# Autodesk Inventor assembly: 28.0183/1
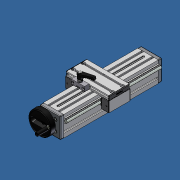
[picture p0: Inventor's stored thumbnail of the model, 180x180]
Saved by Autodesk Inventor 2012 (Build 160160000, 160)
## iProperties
Created: 2007-06
Part Number: 28.0183/1
Document SubType Name: Assembly
Designer: Andy Moles
Description: ADJUSTING UNIT VEW 90 WITH TOP LOCK
Author: Andy Moles
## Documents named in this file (20)
- C:\Andys Backup Data\ANDY'S INVENTOR\INVENTOR LIBRARIES\PARTS LIBRARY\READY FOR USE MODULES LG\28.0183_1 ADJUSTING UNIT VEW 90 WITH TOP LOCK.iam
- C:\Andys Backup Data\ANDY'S INVENTOR\INVENTOR LIBRARIES\PARTS LIBRARY\FASTENING ELEMENTS\NUTS\21.1351 M8 SQUARE NUT.ipt
- C:\Andys Backup Data\ANDY'S INVENTOR\INVENTOR LIBRARIES\PARTS LIBRARY\READY FOR USE MODULES LG\SUBCOMPONENTS\50.1264 BALL BEARING 10X30X9 6200 2RS DIN 625.ipt
- C:\Andys Backup Data\ANDY'S INVENTOR\INVENTOR LIBRARIES\PARTS LIBRARY\READY FOR USE MODULES LG\SUBCOMPONENTS\28.0204 HANDWHEEL 100mm.iam
- C:\Andys Backup Data\ANDY'S INVENTOR\INVENTOR LIBRARIES\PARTS LIBRARY\READY FOR USE MODULES LG\SUBCOMPONENTS\28.0205 BEARING PLATE 90X90 HANDWHEEL SIDE.ipt
- C:\Andys Backup Data\ANDY'S INVENTOR\INVENTOR LIBRARIES\PARTS LIBRARY\READY FOR USE MODULES LG\SUBCOMPONENTS\28.0206 BEARING PLATE 90X90 IDLER SIDE.ipt
- C:\Andys Backup Data\ANDY'S INVENTOR\INVENTOR LIBRARIES\PARTS LIBRARY\FASTENING ELEMENTS\SCREWS CAP\21.1204 M8X25.ipt
- C:\Andys Backup Data\ANDY'S INVENTOR\INVENTOR LIBRARIES\PARTS LIBRARY\READY FOR USE MODULES LG\SUBCOMPONENTS\28.0216_2 90x90 RAIL TOP LOCK.iam
- C:\Andys Backup Data\ANDY'S INVENTOR\INVENTOR LIBRARIES\PARTS LIBRARY\FASTENING ELEMENTS\WASHERS\21.1326 DISC SPRING 20.ipt
- C:\Andys Backup Data\ANDY'S INVENTOR\INVENTOR LIBRARIES\PARTS LIBRARY\READY FOR USE MODULES LG\SUBCOMPONENTS\28.0221_1 ACME SCREW 16X4 TOP LOCK.ipt
- C:\Andys Backup Data\ANDY'S INVENTOR\INVENTOR LIBRARIES\PARTS LIBRARY\READY FOR USE MODULES LG\SUBCOMPONENTS\28.0225_1 LWG 32X45-90 90X19-NSC.ipt
- C:\Andys Backup Data\ANDY'S INVENTOR\INVENTOR LIBRARIES\PARTS LIBRARY\READY FOR USE MODULES LG\SUBCOMPONENTS\28.0126 SLIDE 45X32.ipt
- C:\Andys Backup Data\ANDY'S INVENTOR\INVENTOR LIBRARIES\PARTS LIBRARY\FASTENING ELEMENTS\SCREWS CAP\21.1200 M8X16.ipt
- C:\Andys Backup Data\ANDY'S INVENTOR\INVENTOR LIBRARIES\PARTS LIBRARY\FASTENING ELEMENTS\SCREWS CAP\21.1235 M5X16.ipt
- C:\Andys Backup Data\ANDY'S INVENTOR\INVENTOR LIBRARIES\PARTS LIBRARY\COMPONENTS LG\22.1094 SLIDE RAIL LG.iam
- C:\Andys Backup Data\ANDY'S INVENTOR\INVENTOR LIBRARIES\PARTS LIBRARY\READY FOR USE MODULES LG\SUBCOMPONENTS\28.0255 Nut slide connector 20.ipt
- C:\Andys Backup Data\ANDY'S INVENTOR\INVENTOR LIBRARIES\PARTS LIBRARY\COMPONENTS LR\28.0270_9 SLIDE CLAMPING UNIT 2mm OFFSET..iam
- C:\Andys Backup Data\ANDY'S INVENTOR\INVENTOR LIBRARIES\PARTS LIBRARY\END CAPS\22.1003_1 END CAP 45x32 Z Gray.iam
- C:\Andys Backup Data\ANDY'S INVENTOR\INVENTOR LIBRARIES\PARTS LIBRARY\END CAPS\22.1014_1 END CAP 90X19 GRAY.ipt
- C:\Andys Backup Data\ANDY'S INVENTOR\INVENTOR LIBRARIES\PARTS LIBRARY\READY FOR USE MODULES LG\SUBCOMPONENTS\28.0257 BRONZE NUT 16X4 NOTCHED.ipt
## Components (41 placed, 19 different names)
1. 28.0216_2 90x90 RAIL TOP LOCK:1 [sub-assembly] — Mate:8, Flush:4, Mate:9, Flush:5, Flush:6, Flush:7, Mate:10, Mate:13, Flush:8, Flush:9, Angle:10, Mate:31
2. 50.1264 10X30X9 6200 2RS DIN 625 BALL BEARING:1 — Insert:15, Insert:18
3. 50.1264 10X30X9 6200 2RS DIN 625 BALL BEARING:2 — Insert:14
4. 28.0204 HANDWHEEL 100mm:1 [sub-assembly] — Insert:5, Angle:3, Angle:4
5. 28.0205 BEARING PLATE 90X90 HANDWHEEL SIDE:1 — Insert:5, Insert:6, Insert:7, Insert:8, Insert:9, Insert:15, Flush:5, Flush:7, Mate:10, Angle:4, Angle:11
6. 28.0206 BEARING PLATE 90X90 IDLER SIDE:1 — Insert:10, Insert:11, Insert:12, Insert:13, Insert:14, Flush:6, Mate:13, Flush:8, Flush:9
7. 21.1204  M8 x 25:1 — Insert:6
8. 21.1204  M8 x 25:2 — Insert:7
9. 21.1204  M8 x 25:3 — Insert:8
10. 21.1204  M8 x 25:4 — Insert:13
11. 21.1204  M8 x 25:5 — Insert:9
12. 21.1204  M8 x 25:6 — Insert:12
13. 21.1204  M8 x 25:7 — Insert:11
14. 21.1204  M8 x 25:8 — Insert:10
15. 21.1326 DISC SPRING 20:1 — Insert:17
16. 21.1326 DISC SPRING 20:2 — Insert:16, Insert:18
17. 28.0221_1 ACME SCREW 16X4 TOP LOCK:1 — Insert:16, Insert:17, Angle:3, Mate:33
18. 28.0225_1 LWG 32X45-90 90X19-NSC:1 — Insert:19, Insert:20, Insert:21, Insert:22, Insert:23, Insert:24, Insert:25, Insert:26, Angle:5, Angle:6, Angle:7, Angle:8, Mate:17, Flush:10, Mate:18, Flush:11, Flush:12, Flush:13, Insert:27, Insert:28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
19. 28.0126 SLIDE 45X32:1 — Mate:18, Flush:11, Flush:12, Mate:19, Flush:14, Mate:20, Mate:26, Flush:19, Flush:20, Mate:28, Flush:23, Flush:24
20. 28.0126 SLIDE 45X32:2 — Mate:17, Flush:10, Flush:13, Mate:21, Flush:15, Mate:22, Mate:25, Flush:17, Flush:18, Mate:27, Flush:21, Flush:22
21. 21.1200 M8 x 16:1 — Insert:20
22. 21.1200 M8 x 16:2 — Insert:19
23. 21.1200 M8 x 16:3 — Insert:21
24. 21.1200 M8 x 16:4 — Insert:22
25. 21.1351 M8 SQUARE NUT:2 — Insert:23, Angle:8
26. 21.1351 M8 SQUARE NUT:3 — Insert:24, Angle:7
27. 21.1351 M8 SQUARE NUT:4 — Insert:25, Angle:6
28. 21.1351 M8 SQUARE NUT:5 — Insert:26, Angle:5
29. 21.1235  M5 x 16:1 — Insert:28
30. 21.1235  M5 x 16:2 — Insert:27
31. 22.1094 SLIDE RAIL LG:1 [sub-assembly] — Mate:19, Flush:14, Mate:20
32. 22.1094 SLIDE RAIL LG:2 [sub-assembly] — Mate:21, Flush:15, Mate:22, Mate:31
33. 28.0255 Nut slide connector 20:1 — Insert:29, Angle:9, Mate:32, Angle:12
34. 28.0270_9 SLIDE CLAMPING UNIT 2mm OFFSET.:1 [sub-assembly] — Mate:23, Mate:24, Flush:16
35. 22.1003\1 END CAP 45x32 Z Gray:1 [sub-assembly] — Mate:26, Flush:19, Flush:20
36. 22.1003\1 END CAP 45x32 Z Gray:2 [sub-assembly] — Mate:25, Flush:17, Flush:18
37. 22.1003\1 END CAP 45x32 Z Gray:3 [sub-assembly] — Mate:28, Flush:23, Flush:24
38. 22.1003\1 END CAP 45x32 Z Gray:4 [sub-assembly] — Mate:27, Flush:21, Flush:22
39. 22.1014_1 END CAP 90X19 GRAY:1 — Mate:29, Flush:25, Flush:26
40. 22.1014_1 END CAP 90X19 GRAY:2 — Mate:30, Flush:27, Flush:28
41. 28.0257 BRONZE NUT 16X4 NOTCHED:1 — Mate:32, Mate:33, Angle:12
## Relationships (81: Insert 25, Flush 25, Mate 21, Angle 10)
- Insert:5: 28.0204 HANDWHEEL 100mm:1 ↔ 28.0205 BEARING PLATE 90X90 HANDWHEEL SIDE:1
- Insert:6: 28.0205 BEARING PLATE 90X90 HANDWHEEL SIDE:1 ↔ 21.1204  M8 x 25:1
- Insert:7: 28.0205 BEARING PLATE 90X90 HANDWHEEL SIDE:1 ↔ 21.1204  M8 x 25:2
- Insert:8: 28.0205 BEARING PLATE 90X90 HANDWHEEL SIDE:1 ↔ 21.1204  M8 x 25:3
- Insert:9: 28.0205 BEARING PLATE 90X90 HANDWHEEL SIDE:1 ↔ 21.1204  M8 x 25:5
- Insert:10: 28.0206 BEARING PLATE 90X90 IDLER SIDE:1 ↔ 21.1204  M8 x 25:8
- Insert:11: 28.0206 BEARING PLATE 90X90 IDLER SIDE:1 ↔ 21.1204  M8 x 25:7
- Insert:12: 28.0206 BEARING PLATE 90X90 IDLER SIDE:1 ↔ 21.1204  M8 x 25:6
- Insert:13: 28.0206 BEARING PLATE 90X90 IDLER SIDE:1 ↔ 21.1204  M8 x 25:4
- Mate:8: 28.0216_2 90x90 RAIL TOP LOCK:1
- Flush:4: 28.0216_2 90x90 RAIL TOP LOCK:1
- Mate:9: 28.0216_2 90x90 RAIL TOP LOCK:1
- Insert:14: 50.1264 10X30X9 6200 2RS DIN 625 BALL BEARING:2 ↔ 28.0206 BEARING PLATE 90X90 IDLER SIDE:1
- Insert:15: 50.1264 10X30X9 6200 2RS DIN 625 BALL BEARING:1 ↔ 28.0205 BEARING PLATE 90X90 HANDWHEEL SIDE:1
- Flush:5: 28.0216_2 90x90 RAIL TOP LOCK:1 ↔ 28.0205 BEARING PLATE 90X90 HANDWHEEL SIDE:1
- Flush:6: 28.0216_2 90x90 RAIL TOP LOCK:1 ↔ 28.0206 BEARING PLATE 90X90 IDLER SIDE:1
- Flush:7: 28.0216_2 90x90 RAIL TOP LOCK:1 ↔ 28.0205 BEARING PLATE 90X90 HANDWHEEL SIDE:1
- Mate:10: 28.0216_2 90x90 RAIL TOP LOCK:1 ↔ 28.0205 BEARING PLATE 90X90 HANDWHEEL SIDE:1
- Mate:13: 28.0216_2 90x90 RAIL TOP LOCK:1 ↔ 28.0206 BEARING PLATE 90X90 IDLER SIDE:1
- Flush:8: 28.0216_2 90x90 RAIL TOP LOCK:1 ↔ 28.0206 BEARING PLATE 90X90 IDLER SIDE:1
- Flush:9: 28.0216_2 90x90 RAIL TOP LOCK:1 ↔ 28.0206 BEARING PLATE 90X90 IDLER SIDE:1
- Insert:16: 21.1326 DISC SPRING 20:2 ↔ 28.0221_1 ACME SCREW 16X4 TOP LOCK:1
- Insert:17: 21.1326 DISC SPRING 20:1 ↔ 28.0221_1 ACME SCREW 16X4 TOP LOCK:1
- Insert:18: 50.1264 10X30X9 6200 2RS DIN 625 BALL BEARING:1 ↔ 21.1326 DISC SPRING 20:2
- Angle:3: 28.0204 HANDWHEEL 100mm:1 ↔ 28.0221_1 ACME SCREW 16X4 TOP LOCK:1
- Angle:4: 28.0204 HANDWHEEL 100mm:1 ↔ 28.0205 BEARING PLATE 90X90 HANDWHEEL SIDE:1
- Insert:19: 28.0225_1 LWG 32X45-90 90X19-NSC:1 ↔ 21.1200 M8 x 16:2
- Insert:20: 28.0225_1 LWG 32X45-90 90X19-NSC:1 ↔ 21.1200 M8 x 16:1
- Insert:21: 28.0225_1 LWG 32X45-90 90X19-NSC:1 ↔ 21.1200 M8 x 16:3
- Insert:22: 28.0225_1 LWG 32X45-90 90X19-NSC:1 ↔ 21.1200 M8 x 16:4
- Insert:23: 28.0225_1 LWG 32X45-90 90X19-NSC:1 ↔ 21.1351 M8 SQUARE NUT:2
- Insert:24: 28.0225_1 LWG 32X45-90 90X19-NSC:1 ↔ 21.1351 M8 SQUARE NUT:3
- Insert:25: 28.0225_1 LWG 32X45-90 90X19-NSC:1 ↔ 21.1351 M8 SQUARE NUT:4
- Insert:26: 28.0225_1 LWG 32X45-90 90X19-NSC:1 ↔ 21.1351 M8 SQUARE NUT:5
- Angle:5: 28.0225_1 LWG 32X45-90 90X19-NSC:1 ↔ 21.1351 M8 SQUARE NUT:5
- Angle:6: 28.0225_1 LWG 32X45-90 90X19-NSC:1 ↔ 21.1351 M8 SQUARE NUT:4
- Angle:7: 28.0225_1 LWG 32X45-90 90X19-NSC:1 ↔ 21.1351 M8 SQUARE NUT:3
- Angle:8: 28.0225_1 LWG 32X45-90 90X19-NSC:1 ↔ 21.1351 M8 SQUARE NUT:2
- Mate:17: 28.0225_1 LWG 32X45-90 90X19-NSC:1 ↔ 28.0126 SLIDE 45X32:2
- Flush:10: 28.0225_1 LWG 32X45-90 90X19-NSC:1 ↔ 28.0126 SLIDE 45X32:2
- Mate:18: 28.0225_1 LWG 32X45-90 90X19-NSC:1 ↔ 28.0126 SLIDE 45X32:1
- Flush:11: 28.0225_1 LWG 32X45-90 90X19-NSC:1 ↔ 28.0126 SLIDE 45X32:1
- Flush:12: 28.0225_1 LWG 32X45-90 90X19-NSC:1 ↔ 28.0126 SLIDE 45X32:1
- Flush:13: 28.0225_1 LWG 32X45-90 90X19-NSC:1 ↔ 28.0126 SLIDE 45X32:2
- Insert:27: 28.0225_1 LWG 32X45-90 90X19-NSC:1 ↔ 21.1235  M5 x 16:2
- Insert:28: 28.0225_1 LWG 32X45-90 90X19-NSC:1 ↔ 21.1235  M5 x 16:1
- Mate:19: 28.0126 SLIDE 45X32:1 ↔ 22.1094 SLIDE RAIL LG:1
- Flush:14: 28.0126 SLIDE 45X32:1 ↔ 22.1094 SLIDE RAIL LG:1
- Mate:20: 28.0126 SLIDE 45X32:1 ↔ 22.1094 SLIDE RAIL LG:1
- Mate:21: 28.0126 SLIDE 45X32:2 ↔ 22.1094 SLIDE RAIL LG:2
- Flush:15: 28.0126 SLIDE 45X32:2 ↔ 22.1094 SLIDE RAIL LG:2
- Mate:22: 28.0126 SLIDE 45X32:2 ↔ 22.1094 SLIDE RAIL LG:2
- Insert:29: 28.0225_1 LWG 32X45-90 90X19-NSC:1 ↔ 28.0255 Nut slide connector 20:1
- Angle:9: 28.0225_1 LWG 32X45-90 90X19-NSC:1 ↔ 28.0255 Nut slide connector 20:1
- Mate:23: 28.0225_1 LWG 32X45-90 90X19-NSC:1 ↔ 28.0270_9 SLIDE CLAMPING UNIT 2mm OFFSET.:1
- Mate:24: 28.0225_1 LWG 32X45-90 90X19-NSC:1 ↔ 28.0270_9 SLIDE CLAMPING UNIT 2mm OFFSET.:1
- Flush:16: 28.0225_1 LWG 32X45-90 90X19-NSC:1 ↔ 28.0270_9 SLIDE CLAMPING UNIT 2mm OFFSET.:1
- Mate:25: 28.0126 SLIDE 45X32:2 ↔ 22.1003\1 END CAP 45x32 Z Gray:2
- Flush:17: 28.0126 SLIDE 45X32:2 ↔ 22.1003\1 END CAP 45x32 Z Gray:2
- Flush:18: 28.0126 SLIDE 45X32:2 ↔ 22.1003\1 END CAP 45x32 Z Gray:2
- Mate:26: 28.0126 SLIDE 45X32:1 ↔ 22.1003\1 END CAP 45x32 Z Gray:1
- Flush:19: 28.0126 SLIDE 45X32:1 ↔ 22.1003\1 END CAP 45x32 Z Gray:1
- Flush:20: 28.0126 SLIDE 45X32:1 ↔ 22.1003\1 END CAP 45x32 Z Gray:1
- Mate:27: 28.0126 SLIDE 45X32:2 ↔ 22.1003\1 END CAP 45x32 Z Gray:4
- Flush:21: 28.0126 SLIDE 45X32:2 ↔ 22.1003\1 END CAP 45x32 Z Gray:4
- Flush:22: 28.0126 SLIDE 45X32:2 ↔ 22.1003\1 END CAP 45x32 Z Gray:4
- Mate:28: 28.0126 SLIDE 45X32:1 ↔ 22.1003\1 END CAP 45x32 Z Gray:3
- Flush:23: 28.0126 SLIDE 45X32:1 ↔ 22.1003\1 END CAP 45x32 Z Gray:3
- Flush:24: 28.0126 SLIDE 45X32:1 ↔ 22.1003\1 END CAP 45x32 Z Gray:3
- Mate:29: 28.0225_1 LWG 32X45-90 90X19-NSC:1 ↔ 22.1014_1 END CAP 90X19 GRAY:1
- Flush:25: 28.0225_1 LWG 32X45-90 90X19-NSC:1 ↔ 22.1014_1 END CAP 90X19 GRAY:1
- Flush:26: 28.0225_1 LWG 32X45-90 90X19-NSC:1 ↔ 22.1014_1 END CAP 90X19 GRAY:1
- Mate:30: 28.0225_1 LWG 32X45-90 90X19-NSC:1 ↔ 22.1014_1 END CAP 90X19 GRAY:2
- Flush:27: 28.0225_1 LWG 32X45-90 90X19-NSC:1 ↔ 22.1014_1 END CAP 90X19 GRAY:2
- Flush:28: 28.0225_1 LWG 32X45-90 90X19-NSC:1 ↔ 22.1014_1 END CAP 90X19 GRAY:2
- Angle:10: 28.0216_2 90x90 RAIL TOP LOCK:1 ↔ 28.0225_1 LWG 32X45-90 90X19-NSC:1
- Angle:11: 28.0205 BEARING PLATE 90X90 HANDWHEEL SIDE:1 ↔ 28.0225_1 LWG 32X45-90 90X19-NSC:1
- Mate:31: 28.0216_2 90x90 RAIL TOP LOCK:1 ↔ 22.1094 SLIDE RAIL LG:2
- Mate:32: 28.0255 Nut slide connector 20:1 ↔ 28.0257 BRONZE NUT 16X4 NOTCHED:1
- Mate:33: 28.0221_1 ACME SCREW 16X4 TOP LOCK:1 ↔ 28.0257 BRONZE NUT 16X4 NOTCHED:1
- Angle:12: 28.0255 Nut slide connector 20:1 ↔ 28.0257 BRONZE NUT 16X4 NOTCHED:1
